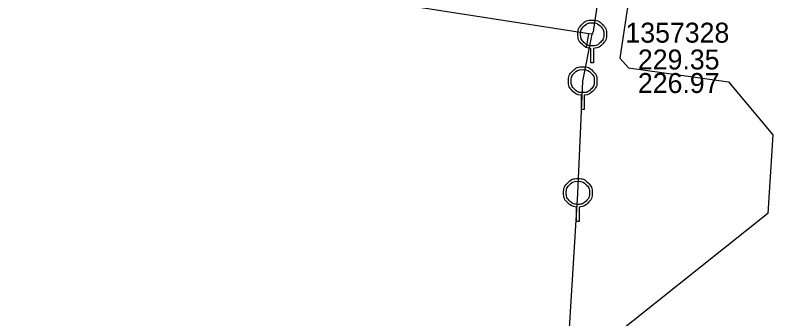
# Model space of a CAD drawing. Extents: x -595129 to -593591, y -1168385 to -1166898.
# Drawn here: x -594603.3 to -594550.1, y -1167314.1 to -1167292.8 of the extents above; entities that cross this region are included whole.
import ezdxf

# ---------------------------------------------------------------- set-up
doc = ezdxf.new("R2010")
doc.units = 0
for name, color, linetype in [('Default', 7, 'Continuous'), ('Identifikace', 7, 'Continuous'), ('Kanalizační přípojka', 7, 'Continuous'), ('Kanalizační stoka', 7, 'Continuous'), ('Kanalizační šachta', 7, 'Continuous'), ('Popis šachty', 7, 'Continuous'), ('V Řad', 7, 'Continuous')]:
    doc.layers.add(name, color=color, linetype=linetype)

msp = doc.modelspace()

# ---------------------------------------------------------------- linework, layer by layer
at = {"layer": 'Default'}
for points in [[(-594562.85, -1167295.113), (-594563.203, -1167295.084), (-594563.463, -1167294.824), (-594563.756, -1167294.533), (-594563.756, -1167294.119), (-594563.756, -1167293.703), (-594563.466, -1167293.41), (-594563.176, -1167293.117), (-594562.758, -1167293.117), (-594562.338, -1167293.117), (-594562.047, -1167293.41), (-594561.756, -1167293.703), (-594561.756, -1167294.119), (-594561.756, -1167294.533), (-594562.049, -1167294.824), (-594562.307, -1167295.084), (-594562.662, -1167295.113)], [(-594562.758, -1167293.303), (-594563.096, -1167293.303), (-594563.333, -1167293.54), (-594563.57, -1167293.778), (-594563.57, -1167294.115), (-594563.57, -1167294.453), (-594563.333, -1167294.691), (-594563.096, -1167294.928), (-594562.758, -1167294.928), (-594562.42, -1167294.928), (-594562.183, -1167294.691), (-594561.945, -1167294.453), (-594561.945, -1167294.115), (-594561.945, -1167293.778), (-594562.182, -1167293.54), (-594562.418, -1167293.303), (-594562.758, -1167293.303)], [(-594563.514, -1167298.396), (-594563.867, -1167298.367), (-594564.127, -1167298.107), (-594564.42, -1167297.816), (-594564.42, -1167297.402), (-594564.42, -1167296.986), (-594564.13, -1167296.693), (-594563.84, -1167296.4), (-594563.422, -1167296.4), (-594563.002, -1167296.4), (-594562.711, -1167296.693), (-594562.42, -1167296.986), (-594562.42, -1167297.402), (-594562.42, -1167297.816), (-594562.713, -1167298.107), (-594562.971, -1167298.367), (-594563.326, -1167298.396)], [(-594563.422, -1167296.586), (-594563.76, -1167296.586), (-594563.997, -1167296.823), (-594564.234, -1167297.06), (-594564.234, -1167297.398), (-594564.234, -1167297.736), (-594563.997, -1167297.973), (-594563.76, -1167298.211), (-594563.422, -1167298.211), (-594563.084, -1167298.211), (-594562.847, -1167297.973), (-594562.609, -1167297.736), (-594562.609, -1167297.398), (-594562.609, -1167297.06), (-594562.846, -1167296.823), (-594563.082, -1167296.586), (-594563.422, -1167296.586)], [(-594563.854, -1167306.236), (-594564.207, -1167306.207), (-594564.467, -1167305.947), (-594564.76, -1167305.656), (-594564.76, -1167305.242), (-594564.76, -1167304.826), (-594564.47, -1167304.533), (-594564.18, -1167304.24), (-594563.762, -1167304.24), (-594563.342, -1167304.24), (-594563.051, -1167304.533), (-594562.76, -1167304.826), (-594562.76, -1167305.242), (-594562.76, -1167305.656), (-594563.053, -1167305.947), (-594563.311, -1167306.207), (-594563.666, -1167306.236)], [(-594563.762, -1167304.426), (-594564.1, -1167304.426), (-594564.337, -1167304.663), (-594564.574, -1167304.9), (-594564.574, -1167305.238), (-594564.574, -1167305.576), (-594564.337, -1167305.813), (-594564.1, -1167306.051), (-594563.762, -1167306.051), (-594563.424, -1167306.051), (-594563.187, -1167305.813), (-594562.949, -1167305.576), (-594562.949, -1167305.238), (-594562.949, -1167304.9), (-594563.186, -1167304.663), (-594563.422, -1167304.426), (-594563.762, -1167304.426)]]:
    msp.add_open_spline(points, degree=3, dxfattribs=at)
at = {"layer": 'Kanalizační přípojka'}
msp.add_lwpolyline([(-594563.147, -1167295.064), (-594562.993, -1167294.076)], dxfattribs=at)
at = {"layer": 'Kanalizační stoka'}
msp.add_line((-594563.762, -1167305.284), (-594563.42, -1167297.4), dxfattribs=at)
for points in [[(-594558.52, -1167265.18), (-594561.904, -1167288.556), (-594561.928, -1167288.722), (-594562.68, -1167293.91), (-594562.756, -1167294.117)], [(-594562.756, -1167294.117), (-594562.993, -1167294.076), (-594609.85, -1167286.79)], [(-594563.42, -1167297.4), (-594562.756, -1167294.117)], [(-594564.636, -1167319.367), (-594564.47, -1167316.609), (-594563.762, -1167305.284)]]:
    msp.add_lwpolyline(points, dxfattribs=at)
at = {"layer": 'Kanalizační šachta'}
for points in [[(-594562.662, -1167295.113), (-594562.662, -1167296.117), (-594562.85, -1167296.117), (-594562.85, -1167295.113)], [(-594563.326, -1167298.396), (-594563.326, -1167299.4), (-594563.514, -1167299.4), (-594563.514, -1167298.396)], [(-594563.666, -1167306.236), (-594563.666, -1167307.24), (-594563.854, -1167307.24), (-594563.854, -1167306.236)]]:
    msp.add_lwpolyline(points, dxfattribs=at)
at = {"layer": 'V Řad'}
msp.add_lwpolyline([(-594559.721, -1167288.497), (-594560.82, -1167295.8), (-594560.22, -1167296.48), (-594553.19, -1167297.46), (-594550.08, -1167301.16), (-594550.43, -1167306.69), (-594563, -1167316.69), (-594568.481, -1167320.944), (-594571.49, -1167323.28), (-594573.53, -1167324.872), (-594578.495, -1167328.758), (-594583.46, -1167332.632), (-594588.74, -1167336.755), (-594593.537, -1167340.523), (-594602.19, -1167347.31), (-594604.637, -1167349.22), (-594609.603, -1167353.096), (-594614.808, -1167357.16), (-594615.446, -1167357.657), (-594619.691, -1167360.971), (-594630.47, -1167369.42), (-594632.795, -1167371.245)], dxfattribs=at)

# ---------------------------------------------------------------- texts
at = {"layer": 'Identifikace'}
msp.add_text('1357328', height=1.4, dxfattribs=at).set_placement((-594560.423, -1167294.702))
at = {"layer": 'Popis šachty'}
for s, p in [('229.35', (-594559.549, -1167296.583)), ('226.97', (-594559.549, -1167298.233))]:
    msp.add_text(s, height=1.4, dxfattribs=at).set_placement(p)

doc.saveas('drawing.dxf')
